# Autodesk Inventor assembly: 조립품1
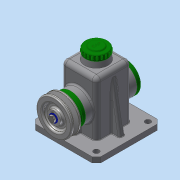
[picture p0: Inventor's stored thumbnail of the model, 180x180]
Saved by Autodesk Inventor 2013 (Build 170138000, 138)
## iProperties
Created: 2018-10
Part Number: 조립품1
Document SubType Name: Assembly
Designer: Administrator
Author: Administrator
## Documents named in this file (14)
- C:\Users\Administrator\Desktop\481013V1008\답안조립품.iam
- C:\Users\Administrator\Desktop\481013V1008\1.본체.ipt
- C:\Users\Administrator\Desktop\481013V1008\V-벨트풀리.ipt
- C:\Users\Administrator\Desktop\481013V1008\뒤커버.ipt
- C:\Users\Administrator\Desktop\481013V1008\멈춤링 15 x 1.ipt
- C:\Users\Administrator\Desktop\481013V1008\베어링 15 x 35 x 11.ipt
- C:\Users\Administrator\Desktop\481013V1008\볼트 M4 x 10.ipt
- C:\Users\Administrator\Desktop\481013V1008\볼트 M6 x 12.ipt
- C:\Users\Administrator\Desktop\481013V1008\상부캡.ipt
- C:\Users\Administrator\Desktop\481013V1008\앞커버.ipt
- C:\Users\Administrator\Desktop\481013V1008\오일실 15 25 7.ipt
- C:\Users\Administrator\Desktop\481013V1008\와셔.ipt
- C:\Users\Administrator\Desktop\481013V1008\축.ipt
- C:\Users\Administrator\Desktop\481013V1008\키 5 x 5 x 14.ipt
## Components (2 placed, 2 different names)
1. 1.본체:1
2. V-벨트풀리:1
